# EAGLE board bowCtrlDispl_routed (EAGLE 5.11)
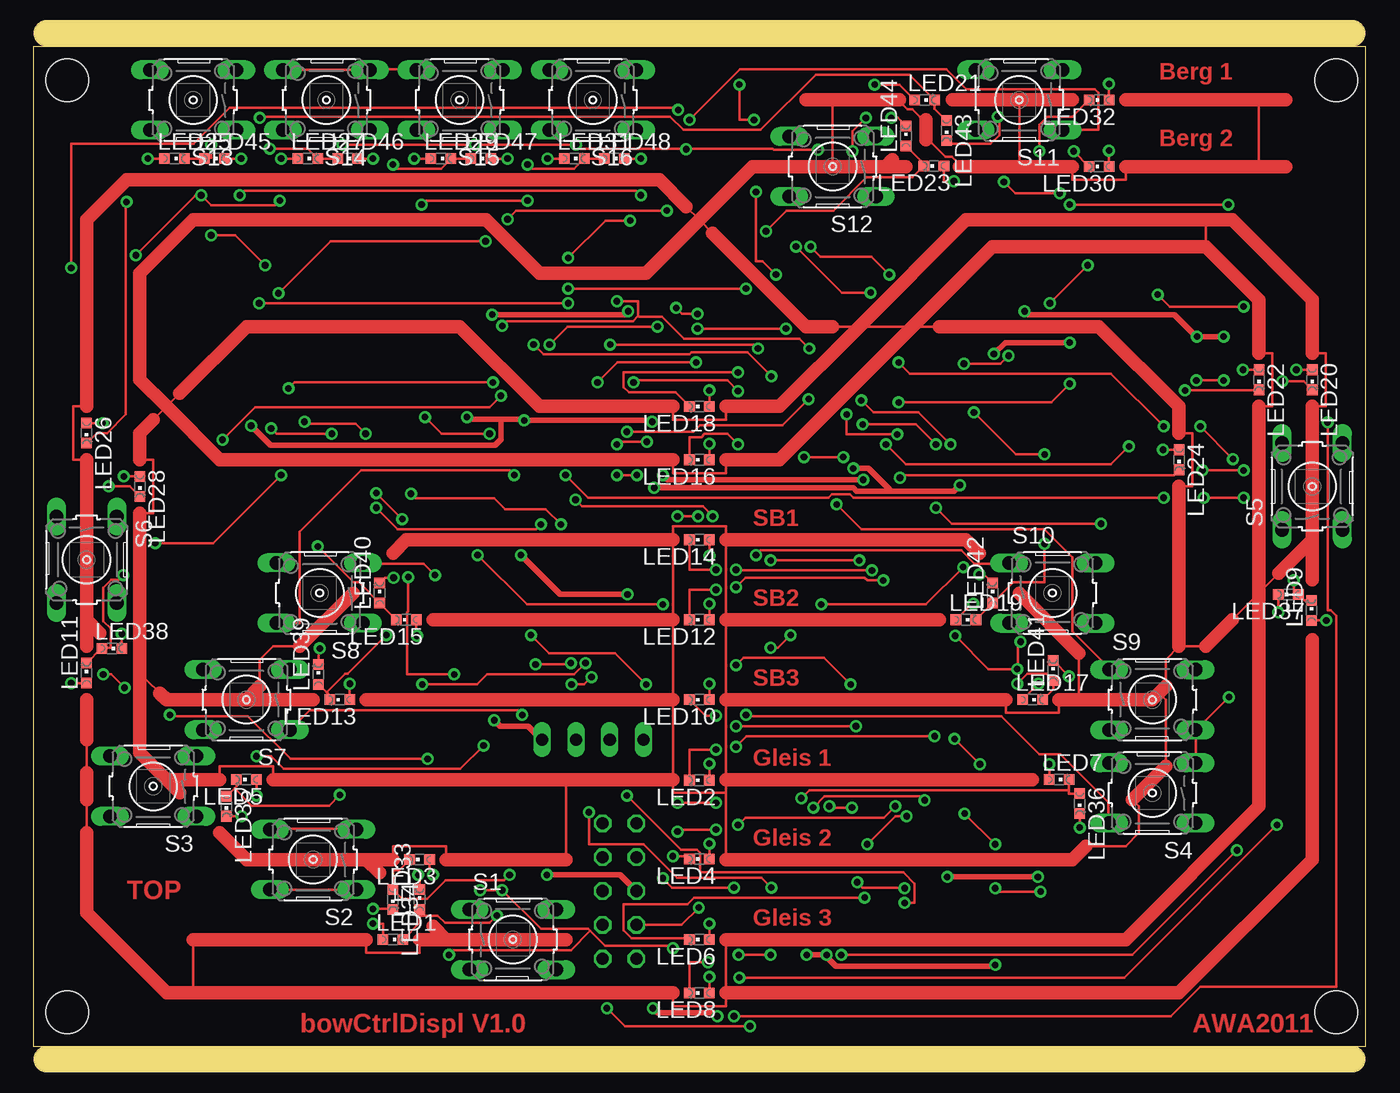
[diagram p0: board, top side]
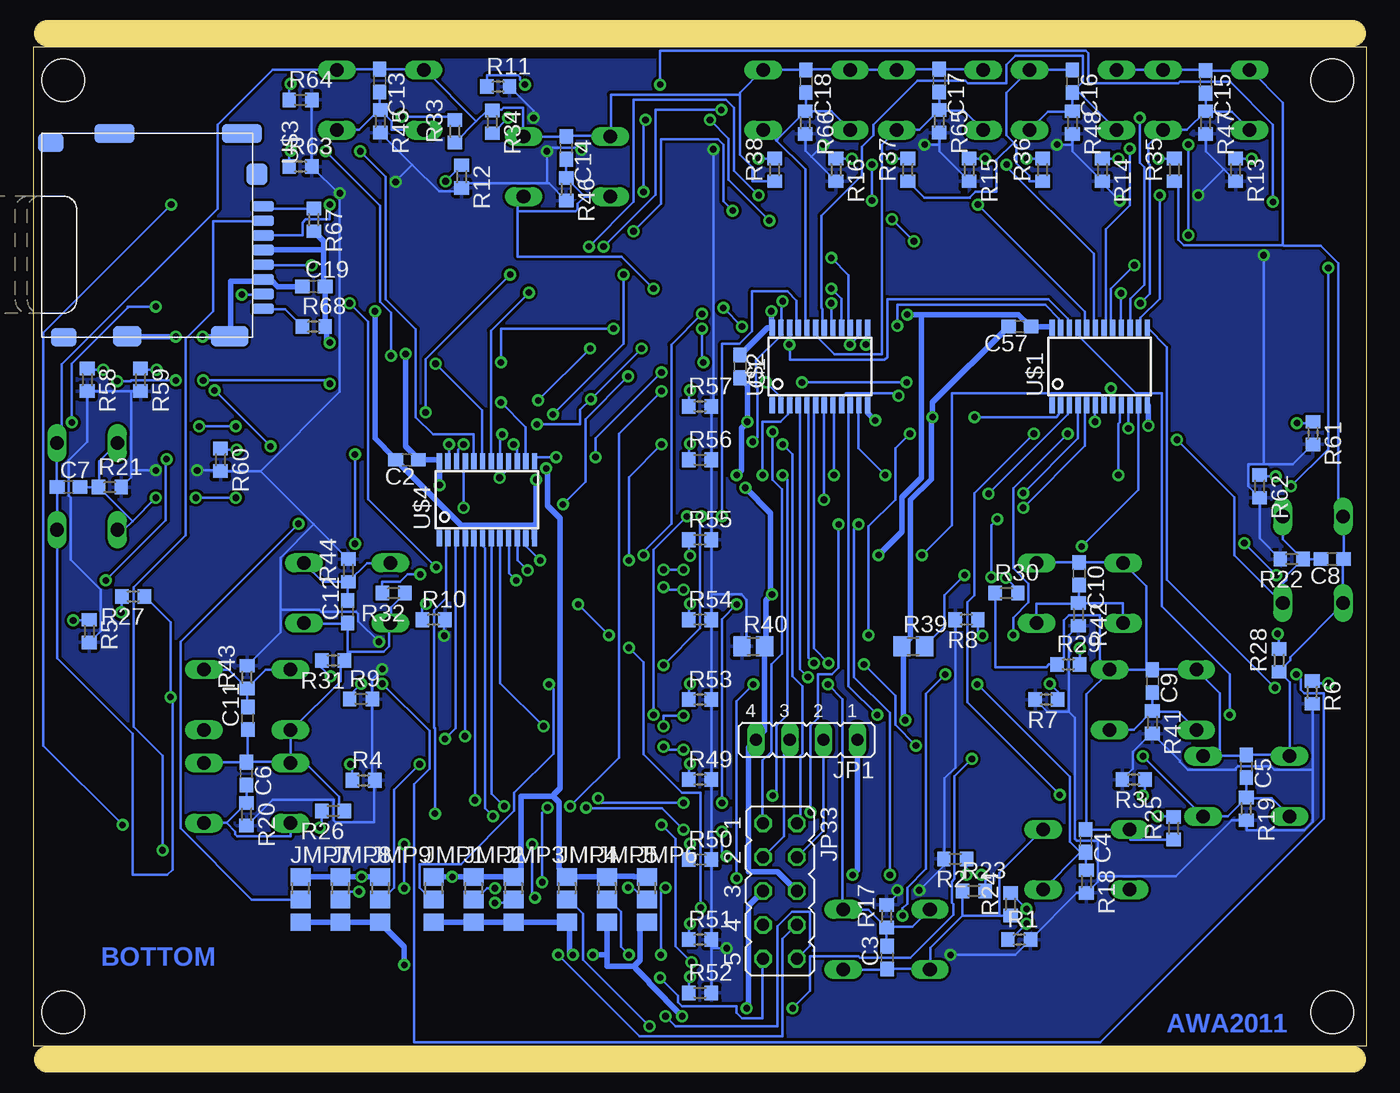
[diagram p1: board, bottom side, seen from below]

Size 100 x 77 mm. Coordinates in mm from the lower left corner, seen from the top.
Outline: 1,77 99,77
Outline: 1,0 99,0
Outline: 0,1 100,1 100,76 0,76 0,1
Copper layers (1*16): Top 0.035mm / dielectric 1.5mm / Bottom 0.035mm
Design rules "ZWILLING *": minimum track width 0.2mm, minimum drill 0.5mm, track to track 0.2mm, track to pad 0.2mm, pad to pad 0.15mm, via to via 0.2mm, smd to smd 0mil, copper to edge 0.2mm, drill to drill 0.2mm, minimum pad ring 0.2mm, minimum via ring 0.2mm, stop-mask expansion 0.1mm, vias tented up to drill 0mil, thermal gap 10mil
Net classes: 1 power: width 0.4 mm; 2 dcc: width 0.4 mm
Holes 3.2 mm at 2.54,73.47 97.79,73.47 2.54,3.54 97.79,3.54

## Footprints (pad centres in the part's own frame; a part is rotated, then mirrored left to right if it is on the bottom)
C0603 = smd 1.1 x 1: 1 -0.85,0; 2 0.85,0
A0R-JMP = smd 1.5 x 1.3: 1 0,1.7; 2 0,0; 3 0,-1.7
JP4 = drill 0.914 long: 1 -3.81,0; 2 -1.27,0; 3 1.27,0; 4 3.81,0
JP5Q = drill 0.914 octagon: 1 -5.08,-1.27; 2 -5.08,1.27; 3 -2.54,-1.27; 4 -2.54,1.27; 5 0,-1.27; 6 0,1.27; 7 2.54,-1.27; 8 2.54,1.27; 9 5.08,-1.27; 10 5.08,1.27
CHIPLED_0603 = smd 0.8 x 0.8: A 0,-0.75; C 0,0.75
R0603 = smd 1 x 1.1: 1 -0.85,0; 2 0.85,0
R0805 = smd 1.3 x 1.5: 1 -0.85,0; 2 0.85,0
B3F-10XX = drill 1.016 long: 1 -3.251,2.261; 2 3.251,2.261; 3 -3.251,-2.261; 4 3.251,-2.261
PW_R-PDSO-G24 = smd 0.4 x 1.2: 1 -3.575,-2.9; 2 -2.925,-2.9; 3 -2.275,-2.9; 4 -1.625,-2.9; 5 -0.975,-2.9; 6 -0.325,-2.9; 7 0.325,-2.9; 8 0.975,-2.9; 9 1.625,-2.9; 10 2.275,-2.9; 11 2.925,-2.9; 12 3.575,-2.9; 13 3.575,2.9; 14 2.925,2.9; 15 2.275,2.9; 16 1.625,2.9; 17 0.975,2.9; 18 0.325,2.9; 19 -0.325,2.9; 20 -0.975,2.9; 21 -1.625,2.9; 22 -2.275,2.9; 23 -2.925,2.9; 24 -3.575,2.9
MICRO_SD_CONNECTOR = smd 0.8 x 1.6: 1 -2.03,8.2; 2 -0.93,8.2; 3 0.17,8.2; 4 1.27,8.2; 5 2.37,8.2; 6 3.47,8.2; 7 4.57,8.2; 8 5.67,8.2 | smd 1.55 x 2.8: 9 7.735,5.7 | smd 1.55 x 2.1: 10 7.735,-2 | smd 1.4 x 1.9: 11 7.81,-6.75; 12 -6.79,-7.75 | smd 1.4 x 3: 13 -7.49,-2.95; 14 -7.49,6.6 | smd 1.6 x 1.55: 15 -4.43,7.725

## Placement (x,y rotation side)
C1  100n  [C0603]  47,52 270 bottom
C2  100n  [C0603]  72,45 180 bottom
C3  100n  [C0603]  35.95,7.65 90 bottom
C4  100n  [C0603]  21.05,16.4 270 bottom
C5  100n  [C0603]  9,22 270 bottom
C6  100n  [C0603]  84.05,21.45 270 bottom
C7  100n  [C0603]  97.4,42.95 0 bottom
C8  100n  [C0603]  2.55,37.55 180 bottom
C9  100n  [C0603]  16.05,28.4 270 bottom
C10  100n  [C0603]  21.55,36.45 270 bottom
C11  100n  [C0603]  83.95,25.6 90 bottom
C12  100n  [C0603]  76.45,33.6 90 bottom
C13  100n  [C0603]  74.05,73.45 270 bottom
C14  100n  [C0603]  60.05,68.4 270 bottom
C15  100n  [C0603]  12.05,73.35 270 bottom
C16  100n  [C0603]  22.05,73.4 270 bottom
C17  100n  [C0603]  32.05,73.45 270 bottom
C18  100n  [C0603]  42.05,73.4 270 bottom
C19  100n  [C0603]  79,58 0 bottom
C57  100n  [C0603]  26,55 180 bottom
JMP1  0R-JUMPA  [A0R-JMP]  70,12 0 bottom
JMP2  0R-JUMPA  [A0R-JMP]  67,12 0 bottom
JMP3  0R-JUMPA  [A0R-JMP]  64,12 0 bottom
JMP4  0R-JUMPA  [A0R-JMP]  60,12 0 bottom
JMP5  0R-JUMPA  [A0R-JMP]  57,12 0 bottom
JMP6  0R-JUMPA  [A0R-JMP]  54,12 0 bottom
JMP7  0R-JUMPA  [A0R-JMP]  80,12 0 bottom
JMP8  0R-JUMPA  [A0R-JMP]  77,12 0 bottom
JMP9  0R-JUMPA  [A0R-JMP]  74,12 0 bottom
JP1  [JP4]  42,24 180 bottom
JP33  [JP5Q]  44,12.64 270 bottom
LED1  [CHIPLED_0603]  27,9 270 top
LED2  [CHIPLED_0603]  50,20.95 90 top
LED3  [CHIPLED_0603]  29,15 90 top
LED4  [CHIPLED_0603]  50,15.05 90 top
LED5  [CHIPLED_0603]  16,21 90 top
LED6  [CHIPLED_0603]  50,9 90 top
LED7  [CHIPLED_0603]  77,21 270 top
LED8  [CHIPLED_0603]  50,5 90 top
LED9  [CHIPLED_0603]  95.95,33.7 0 top
LED10  [CHIPLED_0603]  50,27 90 top
LED11  [CHIPLED_0603]  4,29 0 top
LED12  [CHIPLED_0603]  50,33 90 top
LED13  [CHIPLED_0603]  23,27 90 top
LED14  [CHIPLED_0603]  50,39 90 top
LED15  [CHIPLED_0603]  28,33 90 top
LED16  [CHIPLED_0603]  50,45 90 top
LED17  [CHIPLED_0603]  75,27 270 top
LED18  [CHIPLED_0603]  50,49 90 top
LED19  [CHIPLED_0603]  70,33 270 top
LED20  [CHIPLED_0603]  96,51 180 top
LED21  [CHIPLED_0603]  66.9,72 270 top
LED22  [CHIPLED_0603]  92,51 180 top
LED23  [CHIPLED_0603]  67.6,67.05 90 top
LED24  [CHIPLED_0603]  86,45 180 top
LED25  [CHIPLED_0603]  10.6,67.6 270 top
LED26  [CHIPLED_0603]  4,47 180 top
LED27  [CHIPLED_0603]  20.6,67.6 270 top
LED28  [CHIPLED_0603]  8,43 180 top
LED29  [CHIPLED_0603]  30.6,67.6 270 top
LED30  [CHIPLED_0603]  80,67 90 top
LED31  [CHIPLED_0603]  40.6,67.6 270 top
LED32  [CHIPLED_0603]  80,72 90 top
LED33  [CHIPLED_0603]  29,12 0 top
LED34  [CHIPLED_0603]  27,12 180 top
LED35  [CHIPLED_0603]  14.5,19 180 top
LED36  [CHIPLED_0603]  78.55,19.2 180 top
LED37  [CHIPLED_0603]  94.2,34.9 90 top
LED38  [CHIPLED_0603]  5.9,30.85 270 top
LED39  [CHIPLED_0603]  21.4,28.9 0 top
LED40  [CHIPLED_0603]  26,35 0 top
LED41  [CHIPLED_0603]  76.55,29.2 0 top
LED42  [CHIPLED_0603]  72,35 0 top
LED43  [CHIPLED_0603]  68.55,69.7 180 top
LED44  [CHIPLED_0603]  65.5,69.3 0 top
LED45  [CHIPLED_0603]  13.6,67.6 270 top
LED46  [CHIPLED_0603]  23.6,67.6 270 top
LED47  [CHIPLED_0603]  33.6,67.6 270 top
LED48  [CHIPLED_0603]  43.6,67.6 270 top
R1  220  [R0603]  26.05,9 0 bottom
R2  220  [R0603]  30.85,15.05 180 bottom
R3  220  [R0603]  17.45,21 180 bottom
R4  220  [R0603]  75.25,20.95 0 bottom
R5  220  [R0603]  95.85,32.15 270 bottom
R6  220  [R0603]  4.05,27.55 270 bottom
R7  220  [R0603]  24,27 180 bottom
R8  220  [R0603]  30,33 180 bottom
R9  220  [R0603]  75.45,27.05 0 bottom
R10  220  [R0603]  70,33 0 bottom
R11  220  [R0603]  65.15,73 0 bottom
R12  220  [R0603]  67.9,66.25 270 bottom
R13  220  [R0603]  9.8,66.75 270 bottom
R14  220  [R0603]  19.8,66.75 270 bottom
R15  220  [R0603]  29.8,66.75 270 bottom
R16  220  [R0603]  39.8,66.75 270 bottom
R17  220  [R0603]  36,10.75 90 bottom
R18  220  [R0603]  21,13.35 270 bottom
R19  220  [R0603]  9,18.8 270 bottom
R20  220  [R0603]  84.05,18.4 270 bottom
R21  220  [R0603]  94.3,42.95 0 bottom
R22  220  [R0603]  5.6,37.55 180 bottom
R23  220  [R0603]  29.45,12.65 0 bottom
R24  220  [R0603]  26.7,11.65 90 bottom
R25  220  [R0603]  14.45,17.35 90 bottom
R26  220  [R0603]  77.55,18.65 180 bottom
R27  220  [R0603]  92.55,34.75 180 bottom
R28  220  [R0603]  6.55,29.95 90 bottom
R29  220  [R0603]  22.35,29.65 0 bottom
R30  220  [R0603]  27,35 0 bottom
R31  220  [R0603]  77.55,29.95 180 bottom
R32  220  [R0603]  73,35 180 bottom
R33  220  [R0603]  68.4,69.65 90 bottom
R34  220  [R0603]  65.6,70.35 270 bottom
R35  220  [R0603]  14.4,66.75 90 bottom
R36  220  [R0603]  24.3,66.75 90 bottom
R37  220  [R0603]  34.4,66.75 90 bottom
R38  220  [R0603]  44.4,66.75 90 bottom
R39  0R  [R0805]  34,31 0 bottom
R40  0R  [R0805]  46,31 0 bottom
R41  220  [R0603]  16.05,25.3 270 bottom
R42  220  [R0603]  21.6,33.4 270 bottom
R43  220  [R0603]  84,28.7 90 bottom
R44  220  [R0603]  76.4,36.7 90 bottom
R45  220  [R0603]  74,70.4 270 bottom
R46  220  [R0603]  60.05,65.3 270 bottom
R47  220  [R0603]  12.05,70.3 270 bottom
R48  220  [R0603]  22.05,70.3 270 bottom
R49  220  [R0603]  50,21 0 bottom
R50  220  [R0603]  50,15 0 bottom
R51  220  [R0603]  50,9 0 bottom
R52  220  [R0603]  50,5 0 bottom
R53  220  [R0603]  50,27 0 bottom
R54  220  [R0603]  50,33 0 bottom
R55  220  [R0603]  50,39 0 bottom
R56  220  [R0603]  50,45 0 bottom
R57  220  [R0603]  50,49 0 bottom
R58  220  [R0603]  96,51 270 bottom
R59  220  [R0603]  92,51 270 bottom
R60  220  [R0603]  86,45 270 bottom
R61  220  [R0603]  4,47 270 bottom
R62  220  [R0603]  8,43 270 bottom
R63  220  [R0603]  80,67 0 bottom
R64  220  [R0603]  80,72 0 bottom
R65  220  [R0603]  32.05,70.4 270 bottom
R66  220  [R0603]  42.1,70.3 270 bottom
R67  220  [R0603]  79,63 270 bottom
R68  220  [R0603]  79,55 0 bottom
S1  [B3F-10XX]  36,9 0 top
S2  [B3F-10XX]  21,15 180 top
S3  [B3F-10XX]  9,20.5 180 top
S4  [B3F-10XX]  84,20 180 top
S5  [B3F-10XX]  96,43 90 top
S6  [B3F-10XX]  4,37.5 270 top
S7  [B3F-10XX]  16,27 180 top
S8  [B3F-10XX]  21.5,35 180 top
S9  [B3F-10XX]  84,27 0 top
S10  [B3F-10XX]  76.5,35 0 top
S11  [B3F-10XX]  74,72 180 top
S12  [B3F-10XX]  60,67 180 top
S13  [B3F-10XX]  12,72 180 top
S14  [B3F-10XX]  22,72 180 top
S15  [B3F-10XX]  32,72 180 top
S16  [B3F-10XX]  42,72 180 top
U$1  TCA9555  [PW_R-PDSO-G24]  20,52 0 bottom
U$2  TCA9555  [PW_R-PDSO-G24]  41,52 0 bottom
U$3  MICROSD_SPI_MODE  [MICRO_SD_CONNECTOR]  91,62 270 bottom
U$4  TCA9555  [PW_R-PDSO-G24]  66,42 0 bottom

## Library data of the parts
C1-C19 C57 = rcl
JMP1-JMP9 = jump-0r-smd
JP1 JP33 = jumper
LED1-LED48 = led
R1-R68 = resistor
S1-S16 = switch-omron; MPN: B3F-1000; OC_FARNELL: 176432; OC_NEWARK: 36M3542
U$1 U$2 U$4 = texas_lumi
U$3 = con-molex-microsd

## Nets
FTDI_RX: JP1.2 JP33.4
FTDI_TX: JP1.3 JP33.3
GND [power]: C1.2 C2.2 C19.1 C57.2 JMP1.3 JMP2.3 JMP3.3 JMP4.3 JMP5.3 JMP6.3 JMP7.3 JMP8.3 JMP9.3 JP1.1 JP33.5 R39.1 U$1.12 U$2.12 U$3.6 U$3.9 U$3.10 U$4.12
GNDL: C3.1 C4.1 C5.1 C6.1 C7.1 C8.1 C9.1 C10.1 C11.1 C12.1 C13.1 C14.1 C15.1 C16.1 C17.1 C18.1 R23.1 R24.1 R25.1 R26.1 R27.1 R28.1 R29.1 R30.1 R31.1 R32.1 R33.1 R34.1 R35.1 R36.1 R37.1 R38.1 R39.2 S1.3 S1.4 S2.3 S2.4 S3.3 S3.4 S4.3 S4.4 S5.3 S5.4 S6.3 S6.4 S7.3 S7.4 S8.3 S8.4 S9.3 S9.4 S10.3 S10.4 S11.3 S11.4 S12.3 S12.4 S13.3 S13.4 S14.3 S14.4 S15.3 S15.4 S16.3 S16.4
I2C_SCL: JP33.1 U$1.22 U$2.22 U$4.22
I2C_SDA: JP33.2 U$1.23 U$2.23 U$4.23
N$1: LED1.A R1.1
N$2: LED3.A R2.1
N$3: LED5.A R3.1
N$4: LED7.A R4.1
N$5: LED9.A R5.1
N$6: LED11.A R6.1
N$7: LED13.A R7.1
N$8: LED15.A R8.1
N$9: LED17.A R9.1
N$10: LED19.A R10.1
N$11: LED21.A R11.1
N$12: LED23.A R12.1
N$13: LED25.A R13.1
N$14: LED27.A R14.1
N$15: LED29.A R15.1
N$16: LED31.A R16.1
N$17: U$1.1
N$18: LED44.C R34.2
N$19: LED45.C R35.2
N$20: LED46.C R36.2
N$21: LED47.C R37.2
N$22: LED48.C R38.2
N$23: R67.1 U$3.1
N$31: LED41.C R31.2
N$32: LED42.C R32.2
N$33: LED43.C R33.2
N$34: U$2.1
N$35: R68.1 U$3.8
N$43: LED33.C R23.2
N$44: LED34.C R24.2
N$45: LED35.C R25.2
N$46: LED36.C R26.2
N$47: LED37.C R27.2
N$48: LED38.C R28.2
N$49: LED39.C R29.2
N$50: LED40.C R30.2
N$67: LED2.A R49.1
N$68: LED4.A R50.1
N$69: LED6.A R51.1
N$70: LED8.A R52.1
N$71: LED10.A R53.1
N$72: LED12.A R54.1
N$73: LED14.A R55.1
N$74: LED16.A R56.1
N$75: LED18.A R57.1
N$76: LED20.A R58.1
N$77: LED22.A R59.1
N$78: LED24.A R60.1
N$79: LED26.A R61.1
N$80: LED28.A R62.1
N$81: LED30.A R63.1
N$82: LED32.A R64.1
N$96: U$4.1
SLED0: LED2.C U$4.4
SLED1: LED4.C U$4.5
SLED2: LED6.C U$4.6
SLED3: LED8.C U$4.7
SLED4: LED10.C U$4.8
SLED5: LED12.C U$4.9
SLED6: LED14.C U$4.10
SLED7: LED16.C U$4.11
SLED8: LED18.C U$4.13
SLED9: LED20.C U$4.14
SLED10: LED22.C U$4.15
SLED11: LED24.C U$4.16
SLED12: LED26.C U$4.17
SLED13: LED28.C U$4.18
SLED14: LED30.C U$4.19
SLED15: LED32.C U$4.20
SLEDA0: JMP7.2 U$4.21
SLEDA1: JMP8.2 U$4.2
SLEDA2: JMP9.2 U$4.3
SPI_CS_SD: JP33.8 U$3.2
SPI_SCLK: JP33.7 U$3.5
SPI_SDI: JP33.9 U$3.3
SPI_SDO: JP33.10 U$3.7
TAST0: C3.2 R17.1 S1.1 S1.2 U$2.4
TAST1: C4.2 R18.1 S2.1 S2.2 U$2.5
TAST2: C5.2 R19.1 S3.1 S3.2 U$2.6
TAST3: C6.2 R20.1 S4.1 S4.2 U$2.7
TAST4: C7.2 R21.1 S5.1 S5.2 U$2.8
TAST5: C8.2 R22.1 S6.1 S6.2 U$2.9
TAST6: C9.2 R41.1 S7.1 S7.2 U$2.10
TAST7: C10.2 R42.1 S8.1 S8.2 U$2.11
TAST8: C11.2 R43.1 S9.1 S9.2 U$2.13
TAST9: C12.2 R44.1 S10.1 S10.2 U$2.14
TAST10: C13.2 R45.1 S11.1 S11.2 U$2.15
TAST11: C14.2 R46.1 S12.1 S12.2 U$2.16
TAST12: C15.2 R47.1 S13.1 S13.2 U$2.17
TAST13: C16.2 R48.1 S14.1 S14.2 U$2.18
TAST14: C17.2 R65.1 S15.1 S15.2 U$2.19
TAST15: C18.2 R66.1 S16.1 S16.2 U$2.20
TASTA0: JMP1.2 U$2.21
TASTA1: JMP2.2 U$2.2
TASTA2: JMP3.2 U$2.3
V3_3 [power]: C1.1 C2.1 C19.2 C57.1 JMP1.1 JMP2.1 JMP3.1 JMP4.1 JMP5.1 JMP6.1 JMP7.1 JMP8.1 JMP9.1 JP1.4 JP33.6 R40.2 R67.2 R68.2 U$1.24 U$2.24 U$3.4 U$4.24
VLEDL: R1.2 R2.2 R3.2 R4.2 R5.2 R6.2 R7.2 R8.2 R9.2 R10.2 R11.2 R12.2 R13.2 R14.2 R15.2 R16.2 R17.2 R18.2 R19.2 R20.2 R21.2 R22.2 R40.1 R41.2 R42.2 R43.2 R44.2 R45.2 R46.2 R47.2 R48.2 R49.2 R50.2 R51.2 R52.2 R53.2 R54.2 R55.2 R56.2 R57.2 R58.2 R59.2 R60.2 R61.2 R62.2 R63.2 R64.2 R65.2 R66.2
WLED0: LED1.C LED33.A U$1.4
WLED1: LED3.C LED34.A U$1.5
WLED2: LED5.C LED35.A U$1.6
WLED3: LED7.C LED36.A U$1.7
WLED4: LED9.C LED37.A U$1.8
WLED5: LED11.C LED38.A U$1.9
WLED6: LED13.C LED39.A U$1.10
WLED7: LED15.C LED40.A U$1.11
WLED8: LED17.C LED41.A U$1.13
WLED9: LED19.C LED42.A U$1.14
WLED10: LED21.C LED43.A U$1.15
WLED11: LED23.C LED44.A U$1.16
WLED12: LED25.C LED45.A U$1.17
WLED13: LED27.C LED46.A U$1.18
WLED14: LED29.C LED47.A U$1.19
WLED15: LED31.C LED48.A U$1.20
WLEDA0: JMP4.2 U$1.21
WLEDA1: JMP5.2 U$1.2
WLEDA2: JMP6.2 U$1.3

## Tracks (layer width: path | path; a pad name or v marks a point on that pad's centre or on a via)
FTDI_RX
  Bottom 0.2: JP33.4 42.7,15.2 40.75,17.15 40.75,24 JP1.2
FTDI_TX
  Bottom 0.2: JP33.3 43.7,16.75 43.7,23.6 43.3,24 JP1.3
GND  (via drill 0.5)
  Top 0.4: v89.35,54.25 v87.35,54.25 87.2,54.35 85.65,55.9 74.65,55.9 v74.4,56.15 | v58.05,7.85 v59.55,7.85 59.55,7.7 60.25,7 72.1,7 v72.2,7.1 | v46.45,47.85 46.35,47.95 v36.85,47.95 36.7,48.05 35.1,48.05 | v32.55,48.2 32.7,48.05 35.1,48.05 | v16.35,47.55 17.8,46.1 34.65,46.1 35.1,46.55 35.1,48.05 | v34.6,25.45 35.05,25 37.15,25 38.15,24 JP1.1 | v38.55,13.85 44.05,13.85 45.25,12.65 JP33.5 | v51.35,3.25 51.1,3.5 46.85,3.5 v46.5,3.85 | v62.3,43.5 47.6,43.5 v47.25,43.85
  Bottom 0.4: 62.45,40.1 67.95,40.1 C2.2 72.95,45.15 74.4,46.6 v74.4,56.15 | 62.45,40.1 62.45,39.1 U$4.12 | C19.1 81.7,58 82.2,58.5 82.8,58.5 U$3.6 82.95,58.4 85.25,58.4 85.25,54.45 U$3.9 85.3,54.25 v87.35,54.25 | v89.35,54.25 93,54.25 U$3.10 | JMP7.3 JMP8.3 JMP9.3 73.9,10.15 72.2,8.45 v72.2,7.1 | JMP6.3 54.5,9.8 54.5,7.45 54.95,7 | 54.95,7 57,7 57,7.85 | 57,7.85 JMP5.3 | JMP1.3 JMP2.3 JMP3.3 JMP4.3 59.9,10.15 59.8,10.05 59.8,8.1 v59.55,7.85 | 57,7.85 v58.05,7.85 | C1.2 46.45,50.6 v46.45,47.85 46.55,47.7 46.9,47.35 46.9,44.2 v47.25,43.85 | v36.85,47.95 37.4,48.5 37.4,49.1 U$2.12 | C57.2 32.55,49.3 v32.55,48.2 32.65,48.05 32.65,43.55 34.2,42 34.2,31.65 R39.1 34.75,30.85 34.75,25.6 v34.6,25.45 | v16.35,47.55 16.35,49.05 16.4,49.1 U$1.12 | v38.55,13.85 38.2,14.2 JP1.1 | v51.35,3.25 53.85,5.75 53.85,5.85 54.85,6.85 54.95,7 | v46.5,3.85 46.35,4 46.35,11.55 45.3,12.6 JP33.5 | v62.3,43.5 62.3,40.3 62.35,40.25 62.45,40.1
GNDL  (via drill 0.5)
  Top 0.2: S2.3 24.25,17.3 17.75,17.3 S2.4 | v30.15,36.35 29.3,37.2 24.85,37.2 24.8,37.25 S8.3 | S15.4 28.7,74.3 25.3,74.3 S14.3 25.15,74.25 S14.4 | v89.75,27.2 87.3,24.75 S9.4 87.25,24.65 87.25,22.3 S4.3
  Bottom 0.2: R25.1 17.7,16.5 17.7,17.25 S2.4 17.85,17.25 C4.1 21,17.3 21,27.4 19.25,29.15 S7.3 | 27.55,10.8 30.3,10.8 | 27.55,10.8 R24.1 | 30.3,10.8 R23.1 | 30.3,10.8 32.7,8.4 32.7,6.85 S1.3 32.75,6.8 C3.1 36,6.75 S1.4 | S2.3 24.3,17.25 27.55,14 27.55,10.8 | S8.3 24.75,37.3 C10.1 18.25,37.3 S8.4 18.2,37.2 16.5,35.5 16.5,29.3 C9.1 | R39.2 31.65,32.5 31.65,34.85 v30.15,36.35 | R30.1 27.85,29.45 24,29.45 23.8,29.65 R29.1 22.7,30.15 22.7,32.95 22.3,33.35 20,33.35 20,30.05 19.3,29.35 S7.3 | C9.1 S7.3 | C9.1 16,29.3 12.75,29.3 S7.4 12.7,29.2 11,27.5 11,22.85 S3.3 12.25,22.8 9.05,22.8 C5.1 5.8,22.85 S3.4 5.75,22.8 5.75,28.3 R28.1 5.7,29.95 5.7,30.2 1.75,34.15 S6.4 1.75,37.5 C8.1 1.7,40.75 S6.3 1.75,40.85 2.1,41.2 2.1,59.75 3.4,61.05 6.2,61.05 6.25,61.1 | R35.1 14.1,65.6 14.1,61.5 13.7,61.1 6.25,61.1 | 6.25,61.1 6.25,71.8 8.7,74.25 S13.4 8.8,74.2 C15.1 12.1,74.25 S13.3 15.35,74.25 18.7,74.25 S14.4 | R36.1 25.3,65.9 25.3,66.3 26.25,67.25 26.25,68.6 26.45,68.8 | 26.45,68.8 27,69.35 27,72.55 25.3,74.25 S14.3 25.15,74.25 C16.1 | R37.1 33.15,64.65 29.75,64.65 29.75,64.7 29.35,65.1 27.75,65.1 27.75,67.5 26.45,68.8 | S15.4 28.75,74.3 C17.1 35.25,74.3 S15.3 35.35,74.25 38.65,74.25 S16.4 38.75,74.3 42,74.3 C18.1 45.15,74.25 S16.3 45.3,74.25 47,72.55 47,72.4 | R38.1 46.05,65.9 46.05,66.95 47,67.9 47,72.4 | R32.1 73.2,33.95 73.2,32.75 S10.3 73.25,32.65 73.35,32.55 73.35,31 73.75,30.6 76.45,30.6 | 76.45,30.6 C12.1 76.5,32.7 79.75,32.7 S10.4 | 76.45,30.6 76.45,30.2 R31.1 77,29.65 77,28.4 80.65,24.75 S9.3 80.75,24.7 80.75,22.4 S4.4 | C6.1 83.95,22.4 C11.1 | R26.1 77.1,19.05 77.1,19.7 79.65,22.25 80.7,22.25 S4.4
  Bottom 0.2: C6.1 83.9,22.35 80.75,22.35 S4.4 | R27.1 89.75,32.8 v89.75,27.2 89.6,27.05 89.6,14.25 90,13.85 92.6,13.85 92.6,24.45 98.25,30.1 98.25,39.65 S5.3 C7.1 98.3,43 98.3,46.25 S5.4 98.25,46.35 97.9,46.7 97.9,52.15 86.2,63.85 86.2,70.15 82.1,74.25 77.35,74.25 S11.3 77.25,74.3 C13.1 70.75,74.3 S11.4 70.65,74.25 66.8,70.4 | C6.1 87.25,22.3 S4.3 | 66.8,70.4 66,71.2 R34.1 65.55,71.25 64.9,71.25 64.75,71.4 63.3,71.4 63.3,69.35 S12.3 C14.1 60,69.3 56.75,69.3 S12.4 56.7,69.35 56.7,72.4 47,72.4 | 66.8,70.4 R33.1
I2C_SCL  (via drill 0.5)
  Top 0.2: v67.75,46.15 66.25,47.65 v62.25,47.65 | v54.4,53.35 54.1,53.65 v43.3,53.65 | v44.55,47.1 49.55,47.1 50.05,47.6 56.25,47.6 v58.2,49.55
  Bottom 0.2: 43.25,53.65 43.25,54.9 U$2.22 | 43.25,53.65 43.25,52.5 36.15,52.5 35.95,52.7 35.95,57.05 23.85,57.05 22.4,55.6 22.4,55 22.3,54.9 U$1.22 | v67.75,46.15 68.15,45.75 68.15,45 68.25,44.9 U$4.22 | v62.25,47.65 59,47.65 59,48.75 v58.2,49.55 v54.4,53.35 | v43.3,53.65 43.25,53.65 | v44.55,47.1 44.55,43.5 43.85,42.8 43.85,30.45 44.65,29.65 44.65,23.1 45.3,22.45 45.3,17.75 JP33.1
I2C_SDA  (via drill 0.5)
  Top 0.2: v35.2,55.05 35.55,55.4 45,55.4 45.4,55.8 | 45.4,55.8 45.4,56.9 v43.8,56.9 | v68.85,46.15 66.45,48.55 63.05,48.55 v62.15,49.45 | v58.25,53.35 57.5,54.1 48.85,54.1 47.2,55.75 45.45,55.75 45.4,55.8 | v43.8,46.15 44,46.35 v46.05,46.35
  Bottom 0.2: v35.2,55.05 35.2,56.65 24.1,56.65 23.05,55.6 23.05,55 22.95,54.9 U$1.23 | v43.8,56.9 43.9,56.8 43.9,54.9 U$2.23 44,54.85 44,54.25 45.8,52.45 45.8,50.45 45.7,50.35 45.7,46.7 v46.05,46.35 | v68.85,46.15 68.85,44.95 68.9,44.9 U$4.23 | v58.25,53.35 v62.15,49.45 | v43.8,46.15 43.05,45.4 43.05,28.75 42.3,28 42.3,22.95 42.45,22.8 42.45,18 JP33.2
N$1  (via drill 0.5)
  Top 0.2: LED1.A 26.25,10.2 v25.5,10.2
  Bottom 0.2: v25.5,10.2 26.7,9 R1.1
N$2  (via drill 0.5)
  Top 0.2: LED3.A 29.75,13.85 v30,13.85
  Bottom 0.2: R2.1 v30,13.85
N$3  (via drill 0.5)
  Top 0.2: v16.75,19.8 LED5.A
  Bottom 0.2: v16.75,19.8 16.6,19.95 R3.1
N$4  (via drill 0.5)
  Top 0.2: v76.25,22.15 LED7.A
  Bottom 0.2: v76.25,22.15 76.1,22 R4.1
N$5  (via drill 0.5)
  Top 0.2: v97.05,32.95 LED9.A
  Bottom 0.2: v97.05,32.95 95.85,32.95 R5.1
N$6  (via drill 0.5)
  Top 0.2: v2.85,28.25 LED11.A
  Bottom 0.2: v2.85,28.25 4.05,28.25 R6.1
N$7  (via drill 0.5)
  Top 0.2: v23.75,28.2 LED13.A
  Bottom 0.2: v23.75,28.2 23.15,27.6 R7.1
N$8  (via drill 0.5)
  Top 0.2: LED15.A 28.75,31.8 v28.8,31.8
  Bottom 0.2: v28.8,31.8 29.15,32.15 R8.1
N$9  (via drill 0.5)
  Top 0.2: LED17.A v75.45,28.2
  Bottom 0.2: v75.45,28.2 76.3,27.35 R9.1
N$10  (via drill 0.5)
  Top 0.2: LED19.A 70.45,34.2 v70.55,34.2
  Bottom 0.2: v70.55,34.2 70.85,33.9 R10.1
N$11  (via drill 0.5)
  Top 0.2: LED21.A 65,73.15 v63.15,73.15
  Bottom 0.2: v63.15,73.15 63.5,73.5 63.5,73.7 63.65,73.85 66,73.85 R11.1
N$12  (via drill 0.5)
  Top 0.2: LED23.A 68.35,65.9 v69.1,65.9
  Bottom 0.2: v69.1,65.9 R12.1
N$13  (via drill 0.5)
  Top 0.2: v8.6,67.6 LED25.A
  Bottom 0.2: R13.1 v8.6,67.6
N$14  (via drill 0.5)
  Top 0.2: v18.6,67.6 LED27.A
  Bottom 0.2: R14.1 v18.6,67.6
N$15  (via drill 0.5)
  Top 0.2: v28.6,67.6 LED29.A
  Bottom 0.2: R15.1 v28.6,67.6
N$16  (via drill 0.5)
  Top 0.2: v38.6,67.6 LED31.A
  Bottom 0.2: R16.1 v38.6,67.6
N$18  (via drill 0.5)
  Top 0.2: LED44.C 64.9,70.65 v64.4,70.65
  Bottom 0.2: v64.4,70.65 65.55,69.5 R34.2
N$19  (via drill 0.5)
  Top 0.2: v15.6,67.6 LED45.C
  Bottom 0.2: R35.2 v15.6,67.6
N$20  (via drill 0.5)
  Top 0.2: v25.5,67.6 LED46.C
  Bottom 0.2: R36.2 v25.5,67.6
N$21  (via drill 0.5)
  Top 0.2: v35.6,67.6 LED47.C
  Bottom 0.2: R37.2 v35.6,67.6
N$22  (via drill 0.5)
  Top 0.2: v45.6,67.6 LED48.C
  Bottom 0.2: R38.2 v45.6,67.6
N$23
  Bottom 0.2: R67.1 82.8,63.85 U$3.1
N$31  (via drill 0.5)
  Top 0.2: v77.75,28.75 LED41.C
  Bottom 0.2: v77.75,28.75 78.4,29.4 R31.2
N$32  (via drill 0.5)
  Top 0.2: LED42.C 71.35,36.4 v71,36.4
  Bottom 0.2: v71,36.4 71.95,36.4 72.5,35.85 73.85,35.85 R32.2
N$33  (via drill 0.5)
  Top 0.2: LED43.C 68.8,68.7 71.85,68.7 72.5,69.35 72.5,70.75 v72.4,70.75
  Bottom 0.2: v72.4,70.75 68.4,70.75 R33.2
N$35
  Bottom 0.2: R68.1 81.15,56.3 82.8,56.3 U$3.8
N$43  (via drill 0.5)
  Top 0.2: LED33.C 29,13.85 v28.9,13.85
  Bottom 0.2: v28.9,13.85 28.6,13.55 R23.2
N$44  (via drill 0.5)
  Top 0.2: LED34.C 26.95,11.3 v25.5,11.3
  Bottom 0.2: R24.2 v25.5,11.3
N$45  (via drill 0.5)
  Top 0.2: v15.65,18.25 LED35.C
  Bottom 0.2: v15.65,18.25 14.45,18.25 R25.2
N$46  (via drill 0.5)
  Top 0.2: v78.55,17.4 LED36.C
  Bottom 0.2: v78.55,17.4 78.4,17.55 R26.2
N$47  (via drill 0.5)
  Top 0.2: v93.45,33.55 LED37.C
  Bottom 0.2: v93.45,33.55 93.4,33.6 R27.2
N$48  (via drill 0.5)
  Top 0.2: v6.65,31.95 LED38.C
  Bottom 0.2: v6.65,31.95 6.55,31.85 R28.2
N$49  (via drill 0.5)
  Top 0.2: LED39.C 21.4,30.85 v21.5,30.85
  Bottom 0.2: R29.2 v21.5,30.85
N$50  (via drill 0.5)
  Top 0.2: LED40.C 26.4,36.15 v27.05,36.15
  Bottom 0.2: v27.05,36.15 26.15,35.25 R30.2
N$67  (via drill 0.5)
  Top 0.2: LED2.A v50.75,22.2
  Bottom 0.2: v50.75,22.2 50.85,22.1 R49.1
N$68  (via drill 0.5)
  Top 0.2: LED4.A v50.75,16.2
  Bottom 0.2: v50.75,16.2 50.85,16.1 R50.1
N$69  (via drill 0.5)
  Top 0.2: LED6.A v50.75,10.2
  Bottom 0.2: v50.75,10.2 50.85,10.1 R51.1
N$70  (via drill 0.5)
  Top 0.2: LED8.A v50.75,6.2
  Bottom 0.2: v50.75,6.2 50.85,6.1 R52.1
N$71  (via drill 0.5)
  Top 0.2: LED10.A v50.75,28.2
  Bottom 0.2: v50.75,28.2 50.85,28.1 R53.1
N$72  (via drill 0.5)
  Top 0.2: LED12.A v50.75,34.2
  Bottom 0.2: v50.75,34.2 50.85,34.1 R54.1
N$73  (via drill 0.5)
  Top 0.2: LED14.A v50.75,37.8
  Bottom 0.2: v50.75,37.8 50.85,37.9 R55.1
N$74  (via drill 0.5)
  Top 0.2: LED16.A v50.75,46.2
  Bottom 0.2: v50.75,46.2 50.85,46.1 R56.1
N$75  (via drill 0.5)
  Top 0.2: LED18.A v50.75,50.2
  Bottom 0.2: v50.75,50.2 50.85,50.1 R57.1
N$76  (via drill 0.5)
  Top 0.2: LED20.A v94.8,51.75
  Bottom 0.2: v94.8,51.75 LED20.A R58.1
N$77  (via drill 0.5)
  Top 0.2: v90.8,51.75 LED22.A
  Bottom 0.2: v90.8,51.75 LED22.A R59.1
N$78  (via drill 0.5)
  Top 0.2: v84.8,45.75 LED24.A
  Bottom 0.2: v84.8,45.75 LED24.A R60.1
N$79  (via drill 0.5)
  Top 0.2: v5.2,47.75 LED26.A
  Bottom 0.2: v5.2,47.75 LED26.A R61.1
N$80  (via drill 0.5)
  Top 0.2: v6.8,43.75 LED28.A
  Bottom 0.2: v6.8,43.75 LED28.A R62.1
N$81  (via drill 0.5)
  Top 0.2: v80.75,68.2 LED30.A
  Bottom 0.2: v80.75,68.2 80.85,68.1 R63.1
N$82  (via drill 0.5)
  Top 0.2: v80.75,73.2 LED32.A
  Bottom 0.2: v80.75,73.2 80.85,73.1 R64.1
SLED0  (via drill 0.5)
  Top 0.2: LED2.C 49.25,23.25 v51.25,23.25 | v52.75,23.45 53.55,24.25 v67.65,24.25
  Bottom 0.2: v51.25,23.25 52.75,23.25 v52.75,23.45 | v67.65,24.25 67.65,39.1 U$4.4
SLED1  (via drill 0.5)
  Top 0.2: LED4.C 49.05,15.25 v48,15.25 | v48.35,17.1 48.5,17.25 v51.25,17.25 | v58.55,18.9 59.4,19.75 66.6,19.75 v66.9,19.45
  Bottom 0.2: v48,15.25 48.35,15.6 v48.35,17.1 | v51.25,17.25 52.85,18.85 58.55,18.85 v58.55,18.9 | v66.9,19.45 66.9,39.05 66.95,39.1 U$4.5
SLED2  (via drill 0.5)
  Top 0.2: LED6.C 49.15,9.1 44.9,9.1 44.3,9.7 44.3,11.65 49.1,11.65 49.6,12.15 v62.4,12.15 | v62.6,16.15 64.7,18.25 v65.55,18.25
  Bottom 0.2: v62.4,12.15 62.6,12.35 v62.6,16.15 | v65.55,18.25 66.15,18.85 66.15,38.35 66.3,38.5 66.3,39.1 U$4.6
SLED3  (via drill 0.5)
  Top 0.2: LED8.C 49.25,7.3 v50.65,7.3 | v52.9,17.6 53.45,18.15 63.85,18.15 v64.7,19
  Bottom 0.2: v50.65,7.3 51.85,8.5 51.85,16.55 v52.9,17.6 | v64.7,19 65.65,19.95 65.65,39.1 U$4.7
SLED4  (via drill 0.5)
  Top 0.2: LED10.C 50.45,25.8 v51.25,25.8 | v52.75,25 v61.75,25
  Bottom 0.2: v51.25,25.8 52.75,25.8 v52.75,25 | v61.75,25 65,28.25 65,39.1 U$4.8
SLED5  (via drill 0.5)
  Top 0.2: LED12.C 49.25,35.25 v51.25,35.25 | v52.75,35.45 53.45,36.15 62.4,36.15 62.6,35.95 v63.8,35.95
  Bottom 0.2: v51.25,35.25 52.75,35.25 v52.75,35.45 | v63.8,35.95 64.35,36.5 64.35,39.1 U$4.9
SLED6  (via drill 0.5)
  Top 0.2: LED14.C 49.25,36.75 v51.25,36.75 | v52.75,36.75 52.8,36.7 v62.95,36.7
  Bottom 0.2: v51.25,36.75 v52.75,36.75 | v62.95,36.7 63.7,37.45 63.7,39.1 U$4.10
SLED7  (via drill 0.5)
  Top 0.2: LED16.C 49.25,46.7 50.15,46.7 50.4,46.95 52.1,46.95 v52.9,46.15 | v55.35,37.45 v62,37.45
  Bottom 0.2: v52.9,46.15 55.35,43.7 v55.35,37.45 | v62,37.45 63.05,38.5 63.05,39.1 U$4.11
SLED8  (via drill 0.5)
  Top 0.2: LED18.C 48.2,50.05 44.7,50.05 44.3,50.45 44.3,51.55 v52.9,51.55 | v57.85,45.2 v60.8,45.2
  Bottom 0.2: v52.9,51.55 57.85,46.6 v57.85,45.2 | v60.8,45.2 62.4,45.2 62.4,44.9 U$4.13
SLED9  (via drill 0.5)
  Top 0.2: LED20.C 95.35,50.9 v93.75,50.9 | v87.3,50.95 v89.35,50.95 | v77.8,50.7 76.4,49.3 v64.95,49.3
  Bottom 0.2: v93.75,50.9 92.75,50.9 92.7,50.95 v89.35,50.95 | v87.3,50.95 77.8,50.95 v77.8,50.7 | v64.95,49.3 63.1,47.45 63.1,44.9 U$4.14
SLED10  (via drill 0.5)
  Top 0.2: LED22.C 91.95,50.2 v86.45,50.2 | v82.25,46 80.9,44.65 65.5,44.65 v64,46.15
  Bottom 0.2: v82.25,46 v86.45,50.2 | v64,46.15 63.75,45.9 63.75,44.9 U$4.15
SLED11  (via drill 0.5)
  Top 0.2: LED24.C 85.6,43.85 65.25,43.85 v65.05,43.65
  Bottom 0.2: v65.05,43.65 64.4,44.3 64.4,44.9 U$4.16
SLED12  (via drill 0.5)
  Top 0.2: LED26.C 4.75,47 5.55,47 6.95,48.4 6.95,64.35 v7,64.35 | v53,73.15 53,70.5 v54.1,70.5 | v54.25,65.1 54.25,59.9 54.75,59.9 v55.75,58.9 | v61.05,48.4 61.05,46.9 v64.85,46.9
  Bottom 0.2: v7,64.35 7,70.15 10.2,73.35 14,73.35 14.1,73.25 20.85,73.25 20.85,75.5 21.05,75.7 53,75.7 v53,73.15 | v54.1,70.5 54.25,70.35 v54.25,65.1 | v55.75,58.9 55.75,53.7 v61.05,48.4 | v64.85,46.9 65,46.75 65,44.9 U$4.17
SLED13  (via drill 0.5)
  Top 0.2: LED28.C 7.25,43 v5.65,43 | v2.85,59.4 2.85,68.7 12.05,68.7 14.75,71.4 48.25,71.4 v48.4,71.25 | v57.25,61 60.7,57.55 v62.85,57.55
  Bottom 0.2: v5.65,43 2.85,45.8 v2.85,59.4 | v48.4,71.25 53.35,71.25 53.35,64.9 v57.25,61 | v62.85,57.55 65.7,54.7 65.7,44.9 U$4.18
SLED14  (via drill 0.5)
  Top 0.2: v78.1,68.15 LED30.C | v73.2,52.8 72.6,52.2 v69.85,52.2
  Bottom 0.2: v78.1,68.15 74,64.05 74,56.85 73.2,56.05 v73.2,52.8 | v69.85,52.2 66.35,48.7 66.35,44.9 U$4.19
SLED15  (via drill 0.5)
  Top 0.2: LED32.C 78,70.75 76.1,70.75 75.5,70.15 v75.5,68.15
  Bottom 0.2: v75.5,68.15 73.6,66.25 73.6,57.05 71.35,54.8 71.35,48.2 70.05,46.9 67,46.9 67,44.9 U$4.20
SLEDA0  (via drill 0.5)
  Top 0.2: v67.75,41.4 68.95,40.2 v80.15,40.2
  Bottom 0.2: v67.75,41.4 67.75,44.8 67.65,44.9 U$4.21 | v80.15,40.2 89,31.35 89,17.35 83.65,12 JMP7.2
SLEDA1  (via drill 0.5)
  Top 0.2: v72.2,16.15 v69.9,18.45 | v72.2,12.85 72.45,12.6 v75.6,12.6
  Bottom 0.2: v69.9,18.45 69.9,24.85 69.95,24.9 69.95,33.7 69.05,34.6 69.05,39 68.95,39.1 U$4.2 | v72.2,12.85 v72.2,16.15 | v75.6,12.6 77,12.6 JMP8.2
SLEDA2  (via drill 0.5)
  Top 0.2: v71.05,22.15 v69.15,24.05
  Bottom 0.2: v69.15,24.05 68.35,24.85 68.35,39.05 68.3,39.1 U$4.3 | v71.05,22.15 72.95,20.25 72.95,12.9 73.85,12 JMP9.2
SPI_CS_SD  (via drill 0.5)
  Top 0.2: v90.35,15.7 82.5,7.85 v60.65,7.85
  Bottom 0.2: v90.35,15.7 90.35,22.8 92.5,24.95 92.5,35.45 88.6,39.35 88.6,54.1 86.55,56.15 86.55,62.9 82.8,62.9 U$3.2 | v60.65,7.85 54.55,1.75 43.8,1.75 43.8,9.05 42.75,10.1 JP33.8
SPI_SCLK  (via drill 0.5)
  Top 0.2: v76.3,56.75 v79.15,59.6 | v69.8,36.95 67,34.15 v59.15,34.15 | v56.85,31.85 55.9,30.9 v55.35,30.9 | v49.95,11.4 48.65,10.1 JP33.7
  Bottom 0.2: v79.15,59.6 82.8,59.6 U$3.5 | v76.3,56.75 74.9,55.35 74.9,42.05 v69.8,36.95 | v56.85,31.85 v59.15,34.15 | v55.35,30.9 54.25,29.8 54.25,22.9 51.35,20 49.95,20 v49.95,11.4
SPI_SDI  (via drill 0.5)
  Top 0.2: v89.7,64.15 v77.8,64.15 | v93.35,17.6 81.9,6.15 v53,6.15
  Bottom 0.2: v77.8,64.15 77.8,63.05 79.6,63.05 79.85,62.8 79.85,61.85 82.8,61.85 U$3.3 | v89.7,64.15 99.3,54.55 99.3,23.55 v93.35,17.6 | v53,6.15 51.65,4.8 51.65,4.3 51.35,4 47.25,4 47.25,3.5 46.85,3.1 45.3,3.1 45.3,7.55 JP33.9
SPI_SDO  (via drill 0.5)
  Top 0.2: v84.4,57.4 85.3,56.5 v90.85,56.5 | v97.15,47.8 97.15,33.7 97.4,33.7 97.8,33.3 97.8,5.45 87.6,5.45 85.4,3.25 v52.6,3.25
  Bottom 0.2: v84.4,57.4 82.8,57.4 U$3.7 | v90.85,56.5 92.95,56.5 92.95,56.4 97.15,52.2 v97.15,47.8 | v52.6,3.25 51.85,2.5 44.2,2.5 44.2,10 43.1,11.1 41.75,11.1 41.75,8.55 42.7,7.6 JP33.10
TAST0  (via drill 0.5)
  Top 0.2: v41.9,28.7 41.35,28.15 v40.4,28.15
  Bottom 0.2: C3.2 36,8.55 R17.1 | v41.9,28.7 42.5,29.3 42.5,49 42.6,49.1 U$2.4 | v40.4,28.15 39.3,27.05 39.3,11.3 S1.2 39.15,11.25 37.35,11.25 R17.1 | S1.1 34.05,9.95 35.95,9.95 R17.1
TAST1  (via drill 0.5)
  Top 0.2: S2.2 S2.1 | v41.45,29.75 40.6,28.9 34.05,28.9 33.3,28.15 v29.2,28.15
  Bottom 0.2: R18.1 21.05,14.25 C4.2 | v41.45,29.75 41.85,30.15 41.85,49 41.95,49.1 U$2.5 | v29.2,28.15 22.25,21.2 22.25,16.35 21.1,15.2 C4.2 | S2.1 21.5,15.5 C4.2
TAST2  (via drill 0.5)
  Top 0.2: v40.35,29.75 40.25,29.65 v37.7,29.65 | v33.8,23.55 32.05,21.8 18.8,21.8 17.85,22.75 v16.75,22.75
  Bottom 0.2: R19.1 C5.2 | v40.35,29.75 41.45,30.85 41.45,49 41.35,49.1 U$2.6 | v37.7,29.65 35.35,27.3 35.35,25.1 v33.8,23.55 | v16.75,22.75 12.3,18.3 12.3,18.25 S3.1 12.15,18.25 10.4,18.25 R19.1 | S3.2 7.1,19.6 8.95,19.6 R19.1
TAST3  (via drill 0.5)
  Top 0.2: v40.7,42 41.2,41.5 50.25,41.5 v51,40.75 | v53.5,25.85 53.6,25.75 72.65,25.75 75.5,22.9 77.1,22.9 80.7,19.3 80.7,17.75 S4.2
  Bottom 0.2: C6.2 R20.1 85.55,17.75 | 85.55,17.75 S4.1 | v40.7,42 40.7,49.1 U$2.7 | v51,40.75 53.5,38.25 v53.5,25.85 | 85.55,17.75 84.9,17.1 84.9,16.9 84.75,16.75 80.75,16.75 80.75,17.7 S4.2
TAST4  (via drill 0.5)
  Top 0.2: v39.95,43.85 41.65,42.15 59.7,42.15 59.95,42.4 61.3,42.4 61.55,42.15 v84.85,42.15 | v87.85,42.15 v90.85,42.15
  Bottom 0.2: R21.1 C7.2 | v39.95,43.85 39.95,49.05 40,49.1 U$2.8 | v84.85,42.15 v87.85,42.15 | 92.6,40.4 93.25,39.75 93.7,39.75 S5.1 | v90.85,42.15 92.6,40.4 | 92.6,40.4 R21.1 | S5.2 95.1,44.9 95.1,43 R21.1
TAST5  (via drill 0.5)
  Top 0.2: v35.1,49.8 34.25,48.95 16.65,48.95 v14.2,46.5
  Bottom 0.2: C8.2 R22.1 | R22.1 6.25,39.05 S6.1 | v35.1,49.8 35.1,50 39.05,50 39.25,49.8 39.25,49.2 39.35,49.1 U$2.9 | v14.2,46.5 9.9,42.2 9.9,37.85 6.3,34.25 S6.2 6.95,35 6,35.95 6,36.3 R22.1
TAST6  (via drill 0.5)
  Top 0.2: v36.7,25.85 36.35,26.2 20.75,26.2 19.3,24.75 S7.1
  Bottom 0.2: R41.1 C9.2 | v36.7,25.85 38.85,28 38.85,49 38.75,49.1 U$2.10 | R41.1 17.45,24.75 S7.1 | S7.2 14.1,26.1 16,26.1 R41.1
TAST7  (via drill 0.5)
  Top 0.2: v36.1,43.85 35.75,44.2 24.6,44.2 20,39.6 20,32.75 S8.2
  Bottom 0.2: R42.1 21.55,34.3 C10.2 | R42.1 21.65,34.2 24.75,34.2 S8.1 | v36.1,43.85 38.1,45.85 38.1,49.1 U$2.11 | R42.1 18.25,34.25 S8.2
TAST8  (via drill 0.5)
  Top 0.2: v37.55,53.65 38.3,52.9 49.25,52.9 49.4,53.05 53.6,53.05 v55.4,51.25 | v60.3,41.65 62.15,39.8 75.9,39.8 78,37.7 78,32.15 80.7,29.45 80.7,29.3 S9.1
  Bottom 0.2: C11.2 84,26.5 R43.1 | R43.1 85.4,29.25 S9.2 | v37.55,53.65 37.55,54.8 37.45,54.9 U$2.13 | v55.4,51.25 58.6,48.05 58.6,43.35 v60.3,41.65 | R43.1 82.6,29.25 S9.1
TAST9  (via drill 0.5)
  Top 0.2: v38.75,53.65 40.1,55 v46.85,55 | v48.25,56.4 48.7,55.95 v49.85,55.95 | v54.25,37.85 54.6,38.2 69.65,38.2 70.65,37.2 73.15,37.2 73.2,37.25 S10.1
  Bottom 0.2: R44.1 76.45,35.8 C12.2 | v38.75,53.65 38.2,54.2 38.2,54.8 38.1,54.9 U$2.14 | v46.85,55 v48.25,56.4 | v49.85,55.95 52.15,53.65 52.15,40.2 54.25,38.1 v54.25,37.85 | R44.1 75,37.25 S10.1 | S10.2 78.35,35.85 R44.1
TAST10  (via drill 0.5)
  Top 0.2: v40.15,60.15 42.95,62.95 v44.8,62.95 | v49.25,70.5 53.05,74.3 68.55,74.3 70.05,72.8 79.7,72.8 79.95,72.55 79.95,69.75 77.3,69.75 S11.1
  Bottom 0.2: R45.1 74.05,71.3 C13.2 | v40.15,60.15 38.85,58.85 38.85,55 38.75,54.9 U$2.15 | v44.8,62.95 47.85,66 47.85,69.1 v49.25,70.5 | R45.1 74.1,71.25 75.6,69.75 S11.1 | S11.2 73.15,69.75 73.15,70.4 R45.1
TAST11  (via drill 0.5)
  Top 0.2: v40.15,57.85 v53.5,57.85
  Bottom 0.2: C14.2 R46.1 58.65,64.75 | 58.65,64.75 S12.2 | v40.15,57.85 39.4,57.1 39.4,54.9 U$2.16 | v53.5,57.85 55.9,60.25 63.7,60.25 63.7,63.65 | 63.7,63.65 63.7,64.3 63.3,64.7 S12.1 | 58.65,64.75 59.2,64.2 59.2,63.8 59.35,63.65 63.7,63.65
TAST12  (via drill 0.5)
  Top 0.2: v16.95,56.75 v40.15,56.75
  Bottom 0.2: R47.1 C15.2 | v40.15,56.75 40.15,55 40.05,54.9 U$2.17 | v16.95,56.75 16.25,57.45 16.25,67.15 16.35,67.25 16.35,68.65 15.3,69.7 S13.1 15.15,69.75 13.45,69.75 R47.1 | S13.2 10.1,71.1 12,71.1 R47.1
TAST13
  Bottom 0.2: C16.2 R48.1 22.1,71.1 23.9,71.1 S14.1 | U$2.18 40.7,54.9 40.8,55 40.8,56.3 40.9,56.4 40.9,63.3 37.85,66.35 37.85,68.5 37,69.35 37,70.15 33.7,73.45 30.1,73.45 29.9,73.25 27,73.25 27,74.65 26.35,75.3 21.25,75.3 21.25,73.35 C16.2 | S14.2 21.75,72.75 C16.2
TAST14
  Bottom 0.2: R65.1 C17.2 | U$2.19 41.3,54.9 41.2,54.8 41.2,54.2 39.9,52.9 36.35,52.9 36.35,68.65 35.3,69.7 S15.1 35.15,69.75 33.55,69.75 R65.1 | S15.2 30.2,71.2 32,71.2 R65.1
TAST15
  Bottom 0.2: R66.1 42.05,71.2 C18.2 | 44.25,68.95 45,69.7 45.25,69.7 S16.1 | 44.25,68.95 42.1,66.8 42.1,55 42,54.9 U$2.20 | R66.1 44.2,69.05 44.2,69 44.25,68.95 | S16.2 40.15,71.15 R66.1
TASTA0  (via drill 0.5)
  Top 0.2: v49.9,40.75 v48.35,40.75 | v52.75,29.6 53.3,30.15 59.35,30.15 v61.35,28.15
  Bottom 0.2: v48.35,40.75 48.35,53.7 47.05,53.7 46.1,54.65 46.1,57.65 43.45,57.65 42.75,56.95 42.75,55 42.65,54.9 U$2.21 | v49.9,40.75 50,40.65 50,32.35 v52.75,29.6 | v61.35,28.15 61,27.8 61,22.95 63.95,20 63.95,18.65 67.95,14.65 71.05,14.65 71.05,12.9 70.15,12 JMP1.2
TASTA1  (via drill 0.5)
  Top 0.2: v45.05,50.8 45.2,50.95 52.1,50.95 v52.9,50.15 | v59.75,19 59.85,18.9 v61.45,18.9 | v61.85,13.3 62.25,12.9 65.35,12.9 v65.4,12.85
  Bottom 0.2: v45.05,50.8 44.05,49.8 44.05,49.2 43.95,49.1 U$2.2 | v52.9,50.15 56.1,46.95 56.1,22.65 v59.75,19 | v61.45,18.9 61.85,18.5 v61.85,13.3 | v65.4,12.85 66,12.85 66.85,12 JMP2.2
TASTA2  (via drill 0.5)
  Top 0.2: v43.8,43.85 v45.3,43.85 | v44.55,19.8 48.6,15.75 49.8,15.75 50.05,15.5 50.05,14.05 65.3,14.05 66.15,13.2 66.15,11.75 v65.4,11.75
  Bottom 0.2: v45.3,43.85 45.3,47.85 43.95,47.85 43.4,48.4 43.4,49 43.3,49.1 U$2.3 | v43.8,43.85 43.45,43.5 43.45,25.85 44.25,25.05 44.25,20.1 v44.55,19.8 | v65.4,11.75 64,11.75 JMP3.2
TRACK
  Top 0.2: 74,67 74,72 | 60,67 60,72 | 92,67 92,72 | 88,61 88,63 | 49,64 50,63 51,62 | 9,48 10,49 11,50 | 4,21.5 4,24 | 4,17 4,19.5 | 8,29 10,27 | 93.5,36.5 92,35 88,31 86,31 85,30 85,28 | 78.5,30.5 78.5,27.5 78,27 | 20,31 18,31 17,30 17,28 | 82.5,19.5 83,19 83,17 82,16 79,16 | 85,22 85,27 84.5,27.5 | 73,27 73,26 77,26 77,27 | 12,5 12,9 | 52,9 52,5 52,4 48,4 48,5 | 27,15 27,16 31,16 31,15 | 48,49 48,48 52,48 52,49 | 96,53 97,53 97,49 96,49 | 92,53 93,53 93,49 92,49 | 86,47 87,47 87,43 86,43 | 78,67 78,66 82,66 82,67 | 48,45 48,44 52,44 52,45 | 4,49 3,49 3,45 4,45 | 8,45 9,45 9,41 8,41 | 52,20 48,20 48,21 48,27 48,33 48,39 48,40 52,40 52,39 52,33 52,27 52,21 52,20 | 25,9 25,8 29,8 29,9 | 14,21 14,22 18,22 18,21 | 40,21 40,15 | 60,55 62,55 66,55 68,55 | 52,20 52,15 | 67,70.5 66.55,70.75 66,71.3 65.6,71.3 65.3,71.6 65,72 | 67,69 67.45,68.75 68.45,67.75 68.95,67.75 69.25,67.45 69.5,67
  Top 1: 49,64 47,66 7,66 4,63 4,49 | 48,45 14,45 10,49 8,51 8,59 12,63 34,63 38,59 46,59 50,63 54,67 60,67 64,67 | 64,67 65.5,67 | 64,67 64.5,67.5 | 48,49 38,49 32,55 16,55 11,50 | 51,62 58,55 60,55 | 58,72 60,72 65,72 | 67,70.5 67,69 | 69,72 74,72 78,72 | 82,72 92,72 94,72 | 69.5,67 74,67 78,67 | 82,67 92,67 94,67 | 96,53 96,57 90,63 88,63 70,63 62,55 56,49 52,49 | 92,53 92,57 88,61 72,61 66,55 56,45 52,45 | 86,47 86,49 80,55 68,55 | 9,48 8,47 8,45 | 10,21 8,23 8,29 8,41 | 10,21 11,20 | 14,21 10,21 | 4,45 4,33 | 4,33 4,31 | 4,33 5,32 | 4,19.5 4,21.5 | 4,24 4,27 | 4,17 4,11 10,5 12,5 48,5 | 12,9 25,9 | 29,9 31,9 | 31,9 40,9 | 31,9 30,10 | 52,9 82,9 92,19 92,35 92,49 | 52,5 86,5 96,15 96,31.5 | 96,39 96,49 | 96,39 96,36 | 93.5,36.5 96,39 | 86,31 86,43 | 78.5,30.5 74,35 | 77,27 78,27 84,27 84.5,27.5 85,28 | 88,31 90,33 | 85,22 82.5,19.5 | 52,21 75,21 | 73,27 52,27 | 52,33 68,33 | 52,39 70,39 71,38 | 27,38 28,39 48,39 | 48,33 30,33 | 20,31 24,35 | 52,15 78,15 79,16 | 48,21 40,21 18,21 | 48,27 25,27 | 16,27 10,27 9.5,27.5 | 16,27 21,27 | 16,27 17,28 | 40,15 31,15 | 27,15 25,15 | 25,15 26,14 | 25,15 16,15 14,17
V3_3  (via drill 0.5)
  Top 0.4: v68.6,13.7 v75.4,13.7 | v72.1,52.95 72.95,53.8 v77.8,53.8 | v34.45,55.9 44.4,55.9 v44.65,56.15 | v36.6,37.85 39.55,34.9 v44.6,34.9 | v69.55,43.1 69.1,42.65 64.25,42.65 | 64.25,42.65 61.8,42.65 61.55,42.9 v46.6,42.9 | v61.55,44.35 62.7,44.35 64.25,42.8 64.25,42.65
  Bottom 0.4: JMP9.1 v75.4,13.7 JMP8.1 JMP7.1 | JMP6.1 54.95,13.7 55,13.75 57,13.75 JMP5.1 JMP4.1 60.1,13.85 60.6,14.35 60.6,19.3 61.05,19.75 | JMP1.1 v68.6,13.7 JMP2.1 JMP3.1 63.9,13.85 63.45,14.3 63.45,19.75 61.05,19.75 | R67.2 78.25,61.4 78.25,60.75 | 78.25,60.75 78.25,58.15 C19.2 R68.2 78.05,54.85 78.05,54.05 v77.8,53.8 | U$3.4 82.8,60.75 78.25,60.75 | v72.1,52.95 72.1,46 71.25,45.15 C2.1 69.6,45 69.6,44.9 U$4.24 69.55,44.75 v69.55,43.1 | U$1.24 23.6,54.9 23.6,55 C57.1 25.3,55.1 26.1,55.9 33.4,55.9 | C1.1 44.95,54.9 U$2.24 44.65,55.05 v44.65,56.15 | 33.4,55.9 v34.45,55.9 | JP33.6 42.75,12.65 44.2,14.1 46.35,14.1 46.35,23.4 45.9,23.85 JP1.4 45.15,24.65 R40.2 45.05,31.15 45.05,34.45 v44.6,34.9 44.7,35.05 44.7,41 v46.6,42.9 | v36.6,37.85 34.85,39.6 34.85,42.2 33.4,43.65 33.4,55.9 | v61.55,44.35 61.45,44.25 61.45,41.55 60.5,40.6 60.5,20.35 60.95,19.9 61.05,19.75
VLEDL  (via drill 0.5)
  Top 0.2: v33.55,12.7 v35.2,12.7 38.1,9.8 41.65,9.8 41.8,9.65 | 41.8,9.65 42.9,8.55 47.8,8.55 v48,8.35 | v31.2,7.85 31.55,8.2 40.35,8.2 41.8,9.65 | v18.5,64.45 18.15,64.1 13.35,64.1 v12.6,64.85 12.55,64.8 12.15,64.8 v7.7,60.35 | v23.2,68.65 v33.15,68.65 v40.75,68.65 41.05,68.35 49,68.35 | v69.2,31.8 71.7,29.3 v73.85,29.3 73.9,29.35 73.9,31.35 v74.1,31.35 | v62.5,70.65 61.5,69.65 v61.5,68.15 | v72.85,65.85 73.7,65 v77.05,65 | v87.75,44.2 v90.85,44.2 | 49,68.35 55.5,68.35 55.6,68.25 v58.9,68.25 | v49,68.3 49,68.35
  Bottom 0.2: R7.2 23.95,26.1 22.3,26.1 | 22.3,26.1 22.3,31.85 R42.2 | R3.2 17.5,21.8 17.5,23.1 16.15,24.45 R41.2 14,22.4 14,22.35 13.4,21.75 9.8,21.75 9.8,21.85 9.65,22 7.15,22 6.9,21.75 4,21.75 | 20.15,13.75 14.3,13.75 10.1,17.95 R19.2 8.95,17.9 8.95,17.2 4.65,17.2 4,17.85 4,21.75 | 20.15,13.75 20.15,13.35 R18.2 21.7,12.5 R1.2 26.35,7.85 v31.2,7.85 | R6.2 4,26.65 4,21.75 | 22.3,26.1 21.85,25.65 21.85,16.55 21.7,16.4 20.15,16.4 20.15,13.75 | R17.2 35.2,12.4 v35.2,12.7 | v33.55,12.7 31.7,14.55 R2.2 31.65,15.1 31.65,21.1 30.85,21.9 R8.2 | 49.15,8.35 R51.2 R50.2 R49.2 R53.2 R54.2 49.15,34.9 | 49.15,8.35 R52.2 | 49.15,34.9 R55.2 R56.2 R57.2 49,49.15 v49,68.3 | R40.1 46.5,31.35 46.5,34.5 46.9,34.9 49.15,34.9 | v48,8.35 49.15,8.35 | 41.65,67.75 42.1,68.2 R66.2 | 41.65,67.75 R16.2 | R15.2 32.05,68.15 32.05,68.65 | 32.05,68.65 R65.2 | v40.75,68.65 41.65,67.75 | v33.15,68.65 32.05,68.65 | R22.2 8,39.1 R62.2 8.85,43 8.85,44.65 7.7,44.65 | R61.2 5.5,44.65 7.7,44.65 | 10.7,66.8 12.05,68.15 R47.2 | 10.7,66.8 R13.2 | 22.05,68.65 R48.2 | 22.05,68.65 22.05,68.15 R14.2 19.75,65.85 19.75,65.7 v18.5,64.45 | v12.6,64.85 12.6,64.9 10.7,66.8 | v7.7,60.35 7.7,44.65 | v23.2,68.65 22.05,68.65 | R10.2 69.2,32.95 v69.2,31.8 | v73.85,29.3 74.6,28.55 R9.2 74.6,21.15 R4.2 74.45,20.9 74.45,17.8 77.35,17.8 77.5,17.95 77.5,19.5 82.1,19.5 R20.2 | R5.2 95,32.15 95,35.25 97.25,37.5 97.25,42.15 97.4,42.3 97.4,44.95 96,46.35 R58.2 92.7,50.15 | 92.7,50.15 R59.2 | R21.2 92.7,43.7 92.7,44.2 | 92.7,44.2 92.7,50.15 | R46.2 61.35,65.75 61.5,65.75 | 61.5,65.75 67.9,65.75 R12.2 67.95,65.35 67.95,65.15 69.6,65.15 71.6,67.15 | R11.2 62.5,71.2 v62.5,70.65
  Bottom 0.2: 61.5,65.75 v61.5,68.15 61.45,68.2 61.45,68.4 59.4,68.4 59.25,68.25 v58.9,68.25 | 71.6,67.15 R45.2 | R64.2 R63.2 77.1,64.95 | 83,44.15 79,40.15 | 79,40.15 R44.2 | 83,44.15 R60.2 86.05,44.2 v87.75,44.2 | R43.2 81.5,32.05 81.5,33.75 | 81.5,33.75 81.5,37.65 79,40.15 | 77.1,64.95 77.05,64.9 77.05,50.1 83,44.15 | v72.85,65.85 72.85,65.9 71.6,67.15 | v77.05,65 77.1,64.95 | v90.85,44.2 92.7,44.2 | v74.1,31.35 75.65,32.9 75.65,33.45 75.8,33.6 78.45,33.6 78.6,33.75 81.5,33.75
  pour Bottom: 1,75 99,75 99,1 1,1
WLED0  (via drill 0.5)
  Top 0.2: LED1.C 29,10.25 29,10.8 | 29,10.8 LED33.A | v27.7,40.55 v25.75,42.5 | v28.15,36.2 28.15,33.65 28.05,33.55 28.05,28.9 v31.6,28.9 | v34.8,10.8 34.25,10.25 30.9,10.25 30.35,10.8 29,10.8
  Bottom 0.2: v25.75,42.5 21.65,46.6 21.65,49.1 U$1.4 | v27.7,40.55 28.15,40.1 v28.15,36.2 | v31.6,28.9 33.05,27.45 33.05,14.3 34.45,12.9 34.45,11.7 34.8,11.35 v34.8,10.8
WLED1  (via drill 0.5)
  Top 0.2: LED3.C 27.45,14.2 27,14.2 LED34.A 27.7,12.05 29.55,12.05 30.95,13.45 35.35,13.45 v35.75,13.85 | v25.75,41.4 27.35,39.8 37.75,39.8 v38.1,40.15
  Bottom 0.2: v25.75,41.4 21.1,46.05 21.1,49 21,49.1 U$1.5 | v38.1,40.15 38.45,39.8 38.45,28.7 35.75,26 v35.75,13.85
WLED2  (via drill 0.5)
  Top 0.2: 15.1,20.35 15.25,20.5 LED5.C | LED35.A 15.1,20.35 | v20.35,47.85 20.5,47.7 24.2,47.7 v24.95,46.95 | v23,19.85 22.2,19.05 16.4,19.05 15.1,20.35
  Bottom 0.2: v20.35,47.85 20.35,49.1 U$1.6 | v24.95,46.95 29.4,42.5 29.4,34.85 29.95,34.3 29.95,26.8 v23,19.85
WLED3  (via drill 0.5)
  Top 0.2: 77.75,20.2 77.75,19.95 LED36.A | 77.75,20.2 LED7.C | v33.35,37.85 37.05,34.15 v47.25,34.15 | v48.35,19.25 v51.25,19.25 | v57.65,19.6 58.25,20.2 77.75,20.2
  Bottom 0.2: v33.35,37.85 31.1,40.1 31.1,50 20,50 19.8,49.8 19.8,49.2 19.7,49.1 U$1.7 | v47.25,34.15 48.35,33.05 v48.35,19.25 | v51.25,19.25 57.65,19.25 v57.65,19.6
WLED4  (via drill 0.5)
  Top 0.2: LED9.C 95.4,34.45 LED37.A 94.9,34.95 94.6,34.95 v94.6,35.95 | v19.15,50.35 19.6,50.8 v34.5,50.8 | v42.35,50.8 43.85,52.3 v49.75,52.3 | v49.85,54.85 v56.5,54.85 | v64.95,52.3 65.8,51.45 80.9,51.45 v84.85,47.5 | v87.6,47.5 v90.05,45.05
  Bottom 0.2: v19.15,50.35 19.15,49.2 19.05,49.1 U$1.8 | v34.5,50.8 v42.35,50.8 | v49.75,52.3 49.85,52.4 v49.85,54.85 | v56.5,54.85 64.95,54.85 v64.95,52.3 | v84.85,47.5 v87.6,47.5 | v90.05,45.05 90.1,45 90.1,40.45 v94.6,35.95
WLED5  (via drill 0.5)
  Top 0.2: LED11.C 5.1,30.85 LED38.A 5.2,30.9 5.8,30.9 5.8,32.35 5.25,32.9 5.25,35.4 5.85,36 6.4,36 v6.75,36.35 | v18.6,43.85 13.5,38.75 v9.15,38.75
  Bottom 0.2: v18.6,43.85 18.6,47.7 18.5,47.8 18.5,49 18.4,49.1 U$1.9 | v6.75,36.35 v9.15,38.75
WLED6  (via drill 0.5)
  Top 0.2: 22,27.55 22.25,27.3 LED13.C | LED39.A 22,27.55 | v17.85,47.35 18.25,46.95 v22.4,46.95 | v26.5,31.85 23.6,28.95 23.4,28.95 22,27.55
  Bottom 0.2: v17.85,47.35 17.85,49 17.75,49.1 U$1.10 | v22.4,46.95 26.5,42.85 26.5,36.85 25.35,35.7 25.35,34.3 26.5,33.15 v26.5,31.85
WLED7  (via drill 0.5)
  Top 0.2: LED15.C LED40.A 24.45,35.8 24.05,35.8 v21.35,38.5
  Bottom 0.2: v21.35,38.5 17.1,42.75 17.1,49.1 U$1.11
WLED8  (via drill 0.5)
  Top 0.2: LED17.C 76.55,27.8 LED41.A 76.05,28.95 74.6,28.95 v73.85,28.2 | v6.85,27.9 5.85,28.9 v5.25,28.9
  Bottom 0.2: v6.85,27.9 14.95,36 14.95,53.45 16.4,54.9 U$1.13 | v5.25,28.9 4.9,28.55 4.9,27.75 4.65,27.5 3.2,27.5 3.2,18.05 19.95,1.3 71.45,1.3 71.45,20.65 70.3,21.8 70.3,24.65 v73.85,28.2
WLED9  (via drill 0.5)
  Top 0.2: LED19.C LED42.A 73.55,35.8 75.9,35.8 v75.9,38.7 | v15.5,64.85 15.85,65.2 45.25,65.2 v45.6,64.85 | v58.35,61 59.1,60.25 62.9,60.25 v64.25,58.9 | v70.6,48.55 73.75,45.4 v75.9,45.4
  Bottom 0.2: v15.5,64.85 15.5,57.1 16.95,55.65 16.95,55 17.05,54.9 U$1.14 | v45.6,64.85 47.45,66.7 47.45,71.4 48.05,72 55,72 55,64.35 v58.35,61 | v64.25,58.9 70.6,52.55 v70.6,48.55 | v75.9,45.4 v75.9,38.7
WLED10  (via drill 0.5)
  Top 0.2: LED43.A 67.65,71.35 LED21.C 65.75,73.9 58.75,73.9 54.6,69.75 48.8,69.75 47.8,70.75 17.1,70.75 v17,70.65
  Bottom 0.2: v17,70.65 17,67.3 16.65,66.95 16.65,58.15 17.7,57.1 17.7,54.9 U$1.15
WLED11  (via drill 0.5)
  Top 0.2: LED44.A 66.85,67.2 LED23.C 66,66.2 62.55,66.2 60.05,63.7 56.55,63.7 v55,62.15 | v18.4,57.5 22.3,61.4 v33.95,61.4 | v35.6,63.05 36.25,63.7 v47.55,63.7
  Bottom 0.2: v18.4,57.5 18.4,54.9 U$1.16 | v33.95,61.4 v35.6,63.05 | v47.55,63.7 48.25,64.4 48.25,68.65 48.65,69.05 52.95,69.05 52.95,64.2 v55,62.15
WLED12  (via drill 0.5)
  Top 0.2: LED25.C LED45.A 12.9,67.65 13.35,67.65 v13.35,68.65 | v17.4,59.6 15.15,61.85 v13.35,61.85
  Bottom 0.2: v17.4,59.6 19.15,57.85 19.15,55 19.05,54.9 U$1.17 | v13.35,61.85 v13.35,68.65
WLED13  (via drill 0.5)
  Top 0.2: LED46.A LED27.C 20.6,68.35 v17.75,68.35
  Bottom 0.2: v17.75,68.35 17.75,64.1 19.55,62.3 19.55,55 19.65,54.9 U$1.18
WLED14  (via drill 0.5)
  Top 0.2: LED47.A LED29.C 30.6,66.85 27.3,66.85 v27,67.15
  Bottom 0.2: v27,67.15 27,67 20.45,60.45 20.45,55 20.35,54.9 U$1.19
WLED15  (via drill 0.5)
  Top 0.2: LED48.A LED31.C 40.6,66.85 37.4,66.85 v37.1,67.15 | v29.15,64.15 29.45,64.45 v37.1,64.45
  Bottom 0.2: v29.15,64.15 21.1,56.1 21.1,55 21,54.9 U$1.20 | v37.1,64.45 v37.1,67.15
WLEDA0  (via drill 0.5)
  Top 0.2: v10.25,25.85 10.35,25.75 16.1,25.75 19.3,22.55 v29.6,22.55 | v43.05,3.85 44.4,2.5 v53.8,2.5
  Bottom 0.2: v10.25,25.85 10.25,28.9 15.35,34 15.35,50 17.3,50 21.5,54.2 21.5,54.8 21.6,54.9 U$1.21 | v29.6,22.55 30.9,21.25 30.9,13.55 31.1,13.35 31.1,11.75 31,11.65 31,10.85 34.2,7.65 38,7.65 38.1,7.75 41.75,7.75 41.75,5.15 v43.05,3.85 | v53.8,2.5 58.8,7.5 58.8,10.95 59.85,12 JMP4.2
WLEDA1  (via drill 0.5)
  Top 0.2: v29.4,48.2 30.65,46.95 v34.25,46.95 | v37.35,31.85 38.7,30.5 43.65,30.5 v46,28.15 | v47.25,13.6 47.95,12.9 v52.6,12.9 | v52.95,7.85 v55.35,7.85
  Bottom 0.2: v29.4,48.2 23.25,48.2 23.05,48.4 23.05,49 22.95,49.1 U$1.2 | v34.25,46.95 35.35,45.85 35.35,42 37.35,40 v37.35,31.85 | v46,28.15 47.25,26.9 v47.25,13.6 | v52.6,12.9 52.95,12.55 v52.95,7.85 | v55.35,7.85 55.95,8.45 55.95,11.1 56.85,12 JMP5.2
WLEDA2  (via drill 0.5)
  Top 0.2: v28.35,42.45 28.7,42.1 34.6,42.1 35.4,41.3 38.45,41.3 v39.6,40.15 | v41.7,18.55 41.7,16.15 45.8,16.15 48.3,13.65 54.65,13.65 v55.4,12.9
  Bottom 0.2: v28.35,42.45 22.4,48.4 22.4,49 22.3,49.1 U$1.3 | v39.6,40.15 39.6,29.4 40.1,28.9 41.15,28.9 41.15,25.6 41.7,25.05 v41.7,18.55 | v55.4,12.9 55.05,12.9 54.15,12 JMP6.2

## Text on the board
Top: Berg 1 | Berg 2 | SB1 | SB2 | SB3 | Gleis 1 | Gleis 2 | TOP | Gleis 3 | bowCtrlDispl V1.0 | AWA2011
Bottom: BOTTOM | AWA2011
